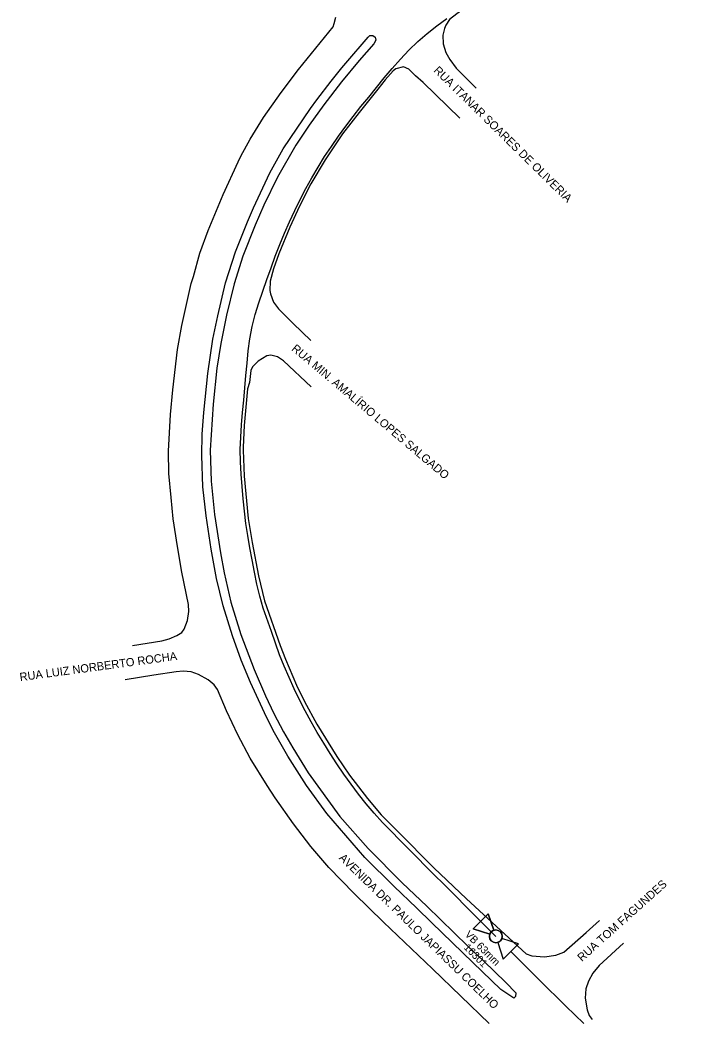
# Model space of a CAD drawing. Extents: x 656692 to 673945, y 7585994 to 7599066.
# Drawn here: x 665465 to 666009, y 7587471 to 7588267 of the extents above; entities that cross this region are included whole.
import ezdxf

# ---------------------------------------------------------------- set-up
doc = ezdxf.new("R2010")
doc.units = 0
for name, color, linetype in [('LOGRADOURO', 7, 'Continuous'), ('LOGRADOURO_TEXTO', 7, 'Continuous'), ('TUBO_PEAD_GN_63', 7, 'Continuous'), ('TUBO_PEAD_GN_90', 7, 'Continuous'), ('VALVULA_PEAD_63', 7, 'Continuous')]:
    doc.layers.add(name, color=color, linetype=linetype)

# ---------------------------------------------------------------- blocks, each defined once
blk = doc.blocks.new('VALVULA_PEAD_DN_9')
at = {"layer": 'VALVULA_PEAD_63'}
for points in [[(-1.14, 0.57), (-4.25, 2.13), (-4.25, -2.13), (-1.14, -0.57)], [(-1.14, -0.57), (-4.25, -2.13), (-4.25, 2.13), (-1.14, 0.57)], [(1.14, -0.57), (4.25, -2.13), (4.25, 2.13), (1.14, 0.57)], [(1.14, -0.57), (4.25, -2.13), (4.25, 2.13), (1.14, 0.57)]]:
    blk.add_lwpolyline(points, dxfattribs=at)
blk.add_circle((0, 0), 1.28, dxfattribs=at)
for start, end in [(90, 270), (153.4349, 206.5651), (270, 90), (0, 26.5651), (333.4349, 0)]:
    blk.add_arc((0, 0), 1.28, start, end, dxfattribs=at)

msp = doc.modelspace()

# ---------------------------------------------------------------- linework, layer by layer
at = {"layer": 'LOGRADOURO'}
for points in [[(666009.24, 7588330.72), (665984.71, 7588354.51), (665979.42, 7588358.7), (665974.59, 7588361.37), (665968.34, 7588361.73), (665963.4, 7588360.61), (665955.77, 7588357.18), (665925.23, 7588339.75), (665895.83, 7588323.24), (665842.55, 7588292.83), (665828.54, 7588283.44), (665812.67, 7588271.92), (665806.82, 7588267.41), (665803.82, 7588262.87), (665802.69, 7588260.13), (665801.3, 7588254.77), (665801.69, 7588247.82), (665803.81, 7588241.04), (665806.96, 7588235.4), (665812.02, 7588228.51), (665827.94, 7588212.52)], [(665554.48, 7587768.75), (665577.9, 7587772.57), (665583.6, 7587774.21), (665589.67, 7587776.71), (665593.62, 7587779.34), (665595.65, 7587781.91), (665598.23, 7587788.8), (665599.17, 7587795.83), (665598.89, 7587801.63), (665593.67, 7587827.17), (665590.15, 7587847.63), (665586.9, 7587869.6), (665585.13, 7587886.58), (665583.37, 7587905.72), (665583.21, 7587923.72), (665584.62, 7587952.7), (665586.52, 7587972.34), (665590.25, 7588004.51), (665593.67, 7588023.76), (665601.13, 7588057.16), (665603.01, 7588062.62), (665607.97, 7588081.31), (665614.58, 7588099.36), (665626.55, 7588127.85), (665638.5, 7588154.02), (665640.77, 7588158.4), (665648.06, 7588172.08), (665658.74, 7588189.31), (665672.84, 7588209.29), (665686.66, 7588227.44), (665714.25, 7588261.45), (665715.01, 7588263.99), (665716.25, 7588269.26)], [(665741.99, 7588253.25), (665743.42, 7588254.57), (665745.79, 7588254.63), (665747.6, 7588253.33), (665748.12, 7588250.82), (665746.61, 7588247.88), (665734.92, 7588234.55), (665720.65, 7588217.7), (665706.62, 7588199.29), (665695.16, 7588183.3), (665684.37, 7588167.36), (665669.75, 7588141.86), (665658.96, 7588119.53), (665651.96, 7588103.59), (665642.18, 7588078.78), (665635.31, 7588056.73), (665629.15, 7588031.83), (665624.65, 7588009.24), (665621.66, 7587989.63), (665618.55, 7587961.07), (665616.27, 7587924.4), (665617.06, 7587899.76), (665619.74, 7587873.2), (665624.54, 7587842.69), (665627.37, 7587826.61), (665632.66, 7587803.42), (665640.57, 7587777.63), (665651.35, 7587749.85), (665660.29, 7587728.66), (665667.02, 7587714.69), (665674.6, 7587700.12), (665681.93, 7587687.34), (665694.25, 7587667.52), (665719.36, 7587632.82), (665741.86, 7587607.17), (665769.17, 7587579.79), (665788.64, 7587561.26), (665821.4, 7587529.46), (665833.73, 7587517.73), (665851.63, 7587500.41), (665859.55, 7587492.27), (665859.25, 7587489.49), (665857.78, 7587488.11), (665847.56, 7587495.07), (665825.37, 7587516.48), (665792.72, 7587548.04), (665780.46, 7587559.86), (665762.66, 7587577.03), (665739.37, 7587599.95), (665709.21, 7587635.03), (665692.86, 7587657.46), (665677.96, 7587680.68), (665666.43, 7587701.29), (665659.42, 7587715.12), (665648.22, 7587739.43), (665640.9, 7587757.17), (665633.95, 7587776.46), (665626.62, 7587800.55), (665621.42, 7587822.13), (665617.07, 7587845.67), (665613.01, 7587871.99), (665610.35, 7587895.24), (665609.67, 7587920.12), (665609.97, 7587937.08), (665611.16, 7587954.47), (665614.31, 7587985.34), (665618.31, 7588012.74), (665622.29, 7588031.27), (665628.49, 7588057.68), (665636.41, 7588082.27), (665645.93, 7588106.23), (665650.61, 7588117.48), (665663.79, 7588145.28), (665674.26, 7588164.3), (665695.99, 7588196.54), (665701.25, 7588203.43), (665712.44, 7588218.14), (665721.14, 7588228.82), (665724.27, 7588232.56), (665741.99, 7588253.25)], [(665814.93, 7588188.8), (665785.67, 7588217.1), (665779.78, 7588222.46), (665774.32, 7588227.7), (665769.98, 7588229.58), (665763.96, 7588228.11), (665761.87, 7588226.45), (665755.48, 7588219.23), (665749.64, 7588211.72), (665734.79, 7588193.32), (665721.68, 7588176.25), (665707.69, 7588155.52), (665696.42, 7588136.57), (665687.32, 7588118.8), (665679.61, 7588101.85), (665670.86, 7588080.83), (665666.58, 7588068.9), (665663.93, 7588058.91), (665663.8, 7588051.4), (665664.26, 7588048.87), (665666.64, 7588042.12), (665670.69, 7588036.85), (665682.4, 7588025.28), (665696.37, 7588011.65)], [(665696.7, 7587974.9), (665674.55, 7587995.4), (665669.79, 7587998.83), (665664.51, 7588000.08), (665661.47, 7587999.56), (665654.37, 7587995.39), (665649.86, 7587990.77), (665648.61, 7587987.89), (665647.47, 7587978.22), (665646.04, 7587973.18), (665643.38, 7587944), (665642.44, 7587926.9), (665642.58, 7587924.35), (665643.38, 7587903.76), (665646.59, 7587869.89), (665649.68, 7587850.88), (665654.67, 7587824.41), (665659.52, 7587804.56), (665671.95, 7587768.77), (665676.12, 7587757.85), (665685.04, 7587737.19), (665691.33, 7587724.16), (665701.14, 7587706.13), (665717.14, 7587680.4), (665727.18, 7587665.67), (665741.36, 7587646.97), (665752.45, 7587634), (665765.46, 7587620.64), (665794.25, 7587591.79), (665820.33, 7587567.03), (665867.69, 7587523.26), (665872.23, 7587521.67), (665882.36, 7587520.99), (665891.21, 7587522.32), (665897.58, 7587524.79), (665915.53, 7587540.37), (665926.07, 7587549.94)], [(665838.33, 7587467.83), (665793.15, 7587511.34), (665754.13, 7587548.6), (665730.87, 7587571.31), (665710.79, 7587592.02), (665696.36, 7587608.72), (665682.52, 7587626.79), (665668.09, 7587647.65), (665661.5, 7587657.29), (665648.15, 7587679.25), (665638.25, 7587697.83), (665629.34, 7587716.85), (665622.15, 7587733.82), (665619.3, 7587737.59), (665614.67, 7587741.45), (665607.02, 7587745.77), (665601.06, 7587747.86), (665594.67, 7587748.5), (665589.13, 7587748.01), (665571.47, 7587745.27), (665548.54, 7587741.62)], [(665945.11, 7587531.79), (665925.72, 7587514), (665920.68, 7587507.86), (665917.24, 7587501.47), (665915.24, 7587495.42), (665914.65, 7587488.07), (665916.16, 7587478.74), (665917.92, 7587474.29), (665920.12, 7587471.04)]]:
    msp.add_lwpolyline(points, dxfattribs=at)
at = {"layer": 'TUBO_PEAD_GN_63'}
msp.add_lwpolyline([(665913.49, 7587468.02), (665906.44, 7587474.89), (665899.38, 7587481.75), (665892.32, 7587488.61), (665885.28, 7587495.48), (665855.58, 7587525.24)], dxfattribs=at)
at = {"layer": 'TUBO_PEAD_GN_90'}
msp.add_lwpolyline([(665843.56, 7587537.28), (665843.56, 7587537.28), (665843.56, 7587537.28), (665843.56, 7587537.28), (665843.56, 7587537.28), (665829.65, 7587551.21), (665822.7, 7587558.17), (665808.79, 7587572.11), (665801.84, 7587579.07), (665794.88, 7587586.04), (665787.93, 7587593.01), (665780.98, 7587599.97), (665774.03, 7587606.94), (665767.08, 7587613.91), (665760.17, 7587620.92), (665753.3, 7587627.97), (665746.74, 7587635.3), (665740.35, 7587642.78), (665734.35, 7587650.59), (665728.4, 7587658.43), (665722.65, 7587666.41), (665717.11, 7587674.55), (665711.8, 7587682.83), (665706.6, 7587691.19), (665701.4, 7587699.55), (665696.49, 7587708.07), (665691.79, 7587716.72), (665687.28, 7587725.47), (665683, 7587734.33), (665679.09, 7587743.36), (665675.19, 7587752.4), (665671.41, 7587761.48), (665668.18, 7587770.78), (665664.95, 7587780.08), (665658.5, 7587798.67), (665655.81, 7587808.13), (665653.48, 7587817.69), (665651.4, 7587827.31), (665649.57, 7587836.98), (665647.75, 7587846.65), (665646.11, 7587856.36), (665644.54, 7587866.07), (665643.47, 7587875.85), (665642.54, 7587885.65), (665641.61, 7587895.45), (665640.85, 7587905.26), (665640.47, 7587915.1), (665640.08, 7587924.93), (665640.52, 7587934.76), (665641.12, 7587944.58), (665642.01, 7587954.39), (665642.91, 7587964.19), (665643.8, 7587973.99), (665644.7, 7587983.79), (665645.59, 7587993.59), (665646.56, 7588003.39), (665647.94, 7588013.13), (665649.8, 7588022.8), (665652.1, 7588032.36), (665654.87, 7588041.81), (665658.06, 7588051.12), (665661.38, 7588060.38), (665664.71, 7588069.65), (665668.03, 7588078.91), (665671.72, 7588088.03), (665675.51, 7588097.12), (665679.43, 7588106.15), (665683.5, 7588115.11), (665687.82, 7588123.95), (665692.3, 7588132.71), (665697.08, 7588141.31), (665702.11, 7588149.77), (665707.27, 7588158.15), (665712.78, 7588166.31), (665718.28, 7588174.47), (665724.13, 7588182.37), (665730.13, 7588190.18), (665736.22, 7588197.91), (665742.4, 7588205.57), (665748.58, 7588213.23), (665754.76, 7588220.89), (665761.2, 7588228.33), (665767.73, 7588235.7), (665774.47, 7588242.87), (665781.55, 7588249.7), (665788.95, 7588256.2), (665796.64, 7588262.33), (665804.58, 7588268.15)], dxfattribs=at)

# ---------------------------------------------------------------- block references
at = {"layer": 'VALVULA_PEAD_63', "xscale": 3.999999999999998, "yscale": 3.999999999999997, "rotation": -45.051931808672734}
msp.add_blockref('VALVULA_PEAD_DN_9', (665843.56, 7587537.28), dxfattribs=at)

# ---------------------------------------------------------------- texts
for s, p in [('VB 63mm', (665818.53, 7587538.29)), ('16301', (665817.63, 7587527.86))]:
    msp.add_text(s, height=6, rotation=314.94807).set_placement(p)
at = {"layer": 'LOGRADOURO_TEXTO'}
for s, rotation, p in [('RUA ITANAR SOARES DE OLIVERIA', 315.50558, (665793.6, 7588226.14)), ('RUA MIN. AMALÍRIO LOPES SALGADO', 319.7816, (665680.5, 7588004.33)), ('RUA LUIZ NORBERTO ROCHA', 7.72727, (665465.08, 7587740.44)), ('AVENIDA DR. PAULO JAPIASSU COELHO', 315.81532, (665718.22, 7587599.17)), ('RUA TOM FAGUNDES', 41.93438, (665912.09, 7587516.76))]:
    msp.add_text(s, height=6.5617, rotation=rotation, dxfattribs=at).set_placement(p)

doc.saveas('drawing.dxf')
